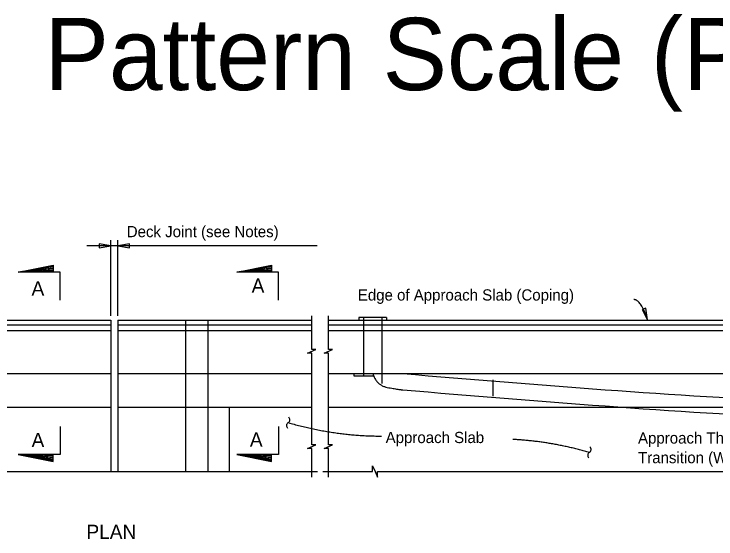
# Model space of a CAD drawing. Extents: x 130583.6 to 130653, y 88618.2 to 88652.9.
# Drawn here: x 130601.81 to 130614.42, y 88643.29 to 88652.71 of the extents above; entities that cross this region are included whole.
import ezdxf

# ---------------------------------------------------------------- set-up
doc = ezdxf.new("R2010")
doc.units = 0
for name, color, linetype in [('Dimension', 7, 'Continuous'), ('Miscellaneous', 7, 'Continuous'), ('TextStructures', 7, 'Continuous'), ('TrafBarrierConc', 7, 'Continuous')]:
    doc.layers.add(name, color=color, linetype=linetype)

msp = doc.modelspace()

# ---------------------------------------------------------------- linework, layer by layer
at = {"layer": 'Dimension'}
for p, q in [((130603.552, 88647.289), (130603.552, 88648.649)), ((130603.674, 88647.289), (130603.674, 88648.649)), ((130607.256, 88648.548), (130603.121, 88648.548)), ((130601.889, 88648.074), (130602.514, 88648.184)), ((130602.514, 88648.171), (130601.889, 88648.074)), ((130601.889, 88648.074), (130602.514, 88648.154)), ((130602.514, 88648.136), (130601.889, 88648.074)), ((130601.889, 88648.074), (130602.514, 88648.118)), ((130602.514, 88648.098), (130601.889, 88648.074)), ((130605.81, 88648.074), (130606.435, 88648.184)), ((130606.435, 88648.171), (130605.81, 88648.074)), ((130605.81, 88648.074), (130606.435, 88648.154)), ((130606.435, 88648.136), (130605.81, 88648.074)), ((130605.81, 88648.074), (130606.435, 88648.118)), ((130606.435, 88648.098), (130605.81, 88648.074)), ((130608.085, 88647.263), (130608.085, 88646.209)), ((130608.418, 88647.263), (130608.418, 88646.08)), ((130602.514, 88644.781), (130601.889, 88644.805)), ((130601.889, 88644.805), (130602.514, 88644.761)), ((130602.514, 88644.743), (130601.889, 88644.805)), ((130601.889, 88644.805), (130602.514, 88644.725)), ((130602.514, 88644.708), (130601.889, 88644.805)), ((130601.889, 88644.805), (130602.514, 88644.695)), ((130606.435, 88644.781), (130605.81, 88644.805)), ((130605.81, 88644.805), (130606.435, 88644.761)), ((130606.435, 88644.743), (130605.81, 88644.805)), ((130605.81, 88644.805), (130606.435, 88644.725)), ((130606.435, 88644.708), (130605.81, 88644.805)), ((130605.81, 88644.805), (130606.435, 88644.695))]:
    msp.add_line(p, q, dxfattribs=at)
for points in [[(130603.552, 88648.548), (130603.344, 88648.583), (130603.344, 88648.513)], [(130603.674, 88648.548), (130603.883, 88648.513), (130603.883, 88648.583)], [(130613.188, 88647.22), (130613.155, 88647.429), (130613.088, 88647.406)]]:
    msp.add_lwpolyline(points, close=True, dxfattribs=at)
for points in [[(130602.639, 88647.574), (130602.639, 88648.074), (130601.889, 88648.074), (130602.514, 88648.199), (130602.514, 88648.074)], [(130606.56, 88647.574), (130606.56, 88648.074), (130605.81, 88648.074), (130606.435, 88648.199), (130606.435, 88648.074)], [(130607.159, 88645.575), (130607.159, 88646.621), (130607.081, 88646.621), (130607.231, 88646.688), (130607.159, 88646.688), (130607.159, 88647.289)], [(130607.459, 88645.575), (130607.459, 88646.621), (130607.381, 88646.621), (130607.531, 88646.688), (130607.459, 88646.688), (130607.459, 88647.289)], [(130607.159, 88644.399), (130607.159, 88644.908), (130607.081, 88644.908), (130607.231, 88644.974), (130607.159, 88644.974), (130607.159, 88645.575)], [(130607.459, 88644.399), (130607.459, 88644.908), (130607.381, 88644.908), (130607.531, 88644.974), (130607.459, 88644.974), (130607.459, 88645.575)], [(130602.639, 88645.305), (130602.639, 88644.805), (130601.889, 88644.805), (130602.514, 88644.68), (130602.514, 88644.805)], [(130606.56, 88645.305), (130606.56, 88644.805), (130605.81, 88644.805), (130606.435, 88644.68), (130606.435, 88644.805)], [(130594.919, 88644.499), (130598.028, 88644.499), (130598.028, 88644.602), (130598.073, 88644.499), (130598.118, 88644.396), (130598.118, 88644.499), (130603.552, 88644.499)], [(130607.359, 88644.499), (130608.251, 88644.499), (130608.251, 88644.602), (130608.296, 88644.499), (130608.341, 88644.396), (130608.341, 88644.499), (130614.232, 88644.499)], [(130614.232, 88644.499), (130618.986, 88644.499), (130618.986, 88644.602), (130619.031, 88644.499), (130619.076, 88644.396), (130619.076, 88644.499), (130623.541, 88644.499)], [(130603.552, 88644.499), (130607.259, 88644.499)]]:
    msp.add_lwpolyline(points, dxfattribs=at)
for centre, start, end in [((130606.706, 88645.427), 298.0989, 49.8261), ((130606.763, 88645.322), 118.0989, 229.8261), ((130612.114, 88644.893), 298.0989, 49.8261), ((130612.171, 88644.788), 118.0989, 229.8261)]:
    msp.add_arc(centre, 0.0596, start, end, dxfattribs=at)
for points in [[(130613.188, 88647.22), (130613.065, 88647.583), (130612.942, 88647.583)], [(130606.735, 88645.375), (130607.572, 88645.134), (130608.409, 88645.134)], [(130612.142, 88644.84), (130611.456, 88645.038), (130610.769, 88645.073)]]:
    msp.add_open_spline(points, degree=2, dxfattribs=at)
at = {"layer": 'Miscellaneous'}
for p, q in [((130608.502, 88647.263), (130608.002, 88647.263)), ((130608.002, 88647.263), (130608.002, 88647.213)), ((130608.502, 88647.263), (130608.502, 88647.213)), ((130607.918, 88646.209), (130607.918, 88646.255)), ((130608.261, 88646.209), (130607.918, 88646.209)), ((130610.418, 88645.85), (130610.418, 88646.142))]:
    msp.add_line(p, q, dxfattribs=at)
msp.add_open_spline([(130608.252, 88646.255), (130608.322, 88646.043), (130608.715, 88645.97), (130608.796, 88645.963)], degree=2, dxfattribs=at)
for points in [[(130608.796, 88646.255), (130616.064, 88645.747), (130622.314, 88645.63), (130624.006, 88645.63)], [(130608.796, 88645.963), (130616.061, 88645.455), (130622.312, 88645.338), (130624.006, 88645.338)]]:
    msp.add_spline(points, degree=3, dxfattribs=at)
at = {"layer": 'TrafBarrierConc'}
for p, q in [((130593.823, 88647.213), (130603.552, 88647.213)), ((130603.552, 88647.213), (130603.552, 88644.499)), ((130603.674, 88647.213), (130603.674, 88644.499)), ((130603.674, 88647.213), (130607.159, 88647.213)), ((130604.894, 88647.213), (130604.894, 88644.499)), ((130605.292, 88647.213), (130605.292, 88644.499)), ((130607.459, 88647.213), (130623.44, 88647.213)), ((130593.823, 88647.13), (130603.552, 88647.13)), ((130603.674, 88647.13), (130607.159, 88647.13)), ((130607.459, 88647.13), (130623.44, 88647.13)), ((130593.823, 88647.026), (130603.552, 88647.026)), ((130603.674, 88647.026), (130607.159, 88647.026)), ((130607.459, 88647.026), (130623.44, 88647.026)), ((130593.823, 88646.255), (130603.552, 88646.255)), ((130603.674, 88646.255), (130607.159, 88646.255)), ((130607.459, 88646.255), (130623.44, 88646.255)), ((130593.823, 88645.651), (130603.552, 88645.651)), ((130603.674, 88645.651), (130607.159, 88645.651)), ((130605.675, 88645.651), (130605.675, 88644.499)), ((130607.459, 88645.651), (130620.44, 88645.651))]:
    msp.add_line(p, q, dxfattribs=at)

# ---------------------------------------------------------------- texts
at = {"layer": 'TextStructures'}
for s, height, p in [('Pattern Scale (PS) = ', 1.296, (130602.361, 88651.343)), ('Deck Joint (see Notes)', 0.2016, (130603.837, 88648.703)), ('Edge of Approach Slab (Coping)', 0.2016, (130607.985, 88647.566)), ('Approach Slab', 0.2016, (130608.485, 88645.008)), ('Approach Thrie-Beam Guardrail ', 0.2016, (130613.016, 88644.999)), ('Transition (When called for in Plans)', 0.2016, (130613.016, 88644.647)), ('PLAN', 0.256, (130603.113, 88643.287))]:
    msp.add_text(s, height=height, dxfattribs=at).set_placement(p)
for p in [(130606.079, 88647.706), (130602.127, 88647.656), (130602.128, 88644.935), (130606.047, 88644.944)]:
    msp.add_text('A', height=0.256, rotation=360, dxfattribs=at).set_placement(p)

doc.saveas('drawing.dxf')
